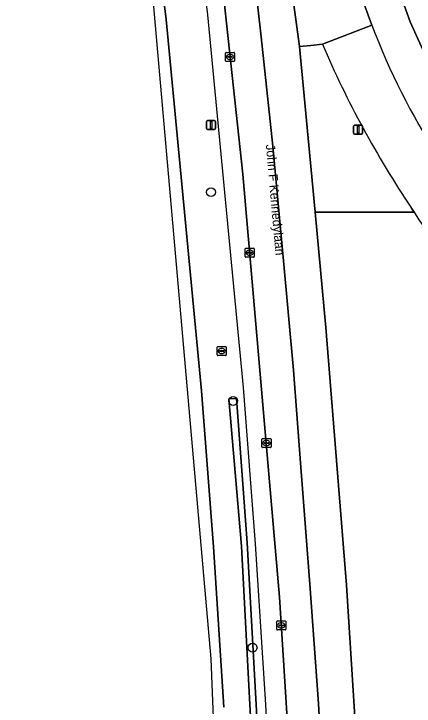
# Model space of a CAD drawing. Extents: x 162082 to 163401, y 388089 to 388636.
# Drawn here: x 162082.4 to 162126.4, y 388303.5 to 388379.6 of the extents above; entities that cross this region are included whole.
import ezdxf

# ---------------------------------------------------------------- set-up
doc = ezdxf.new("R2010")
doc.units = 0
for name, color, linetype in [('IMGEO_Berm_groen', 7, 'Continuous'), ('IMGEO_Boom', 7, 'Continuous'), ('IMGEO_Groenvoorziening', 7, 'Continuous'), ('IMGEO_Haag', 7, 'Continuous'), ('IMGEO_Hek', 7, 'Continuous'), ('IMGEO_Kolk', 7, 'Continuous'), ('IMGEO_Lichtmast', 7, 'Continuous'), ('IMGEO_Loofbos', 7, 'Continuous'), ('IMGEO_Openbare_ruimte_label', 7, 'Continuous'), ('IMGEO_Rijbaan_regionaal_gesloten', 7, 'Continuous'), ('IMGEO_Rioolput', 7, 'Continuous')]:
    doc.layers.add(name, color=color, linetype=linetype)

msp = doc.modelspace()

# ---------------------------------------------------------------- linework, layer by layer
at = {"layer": 'IMGEO_Berm_groen'}
for points in [[(162089.344, 388451.187), (162094.693, 388414.588), (162097.831, 388389.672), (162099.12, 388379.04), (162103.019, 388338.152), (162104.342, 388320.988), (162105.469, 388303.355)], [(162112.999, 388293.402), (162111.592, 388315.455), (162107.552, 388361.994), (162105.216, 388383.751), (162101.034, 388417.69), (162098.392, 388435.629)], [(162158.27, 388342.635), (162154.648, 388344.026), (162150.415, 388346.266), (162146.042, 388349.218), (162141.488, 388353.516), (162137.25, 388358.462), (162133.596, 388363.93), (162129.315, 388371.379), (162125.988, 388378.753), (162122.707, 388387.868), (162120.457, 388395.943), (162118.359, 388404.463), (162117.835, 388406.126), (162116.603, 388420.123), (162123.796, 388423.745), (162124.571, 388428.394), (162120.982, 388427.776)], [(162119.679, 388384.539), (162120.659, 388381.443), (162121.76, 388378.389)], [(162116.321, 388376.305), (162115.03, 388376.174), (162113.812, 388376.05), (162115.514, 388357.816), (162126.399, 388357.816), (162126.249, 388358.048), (162126.1, 388358.281)], [(162126.399, 388357.816), (162115.514, 388357.816), (162116.697, 388345.147), (162118.955, 388316.778), (162120.757, 388288.379), (162121.367, 388274.924), (162122.052, 388250), (162122.739, 388224.991), (162122.955, 388200.63), (162122.882, 388179.99), (162122.587, 388168.062), (162122.56, 388166.951), (162122.56, 388166.951)]]:
    msp.add_lwpolyline(points, dxfattribs=at)
msp.add_lwpolyline([(162110.975, 388250.254), (162110.214, 388270.794), (162108.335, 388303.624), (162107.41, 388321.076), (162106.04, 388337.271), (162106.888, 388337.32), (162108.037, 388321.434), (162109.051, 388303.654), (162110.766, 388270.838), (162111.602, 388250.03), (162111.788, 388226.246), (162111.192, 388226.261)], close=True, dxfattribs=at)
for centre, radius, start, end in [((162198.196, 388407.679), 81.856, 200.96672, 223.60171), ((162218.961, 388420.328), 111.683, 203.21481, 213.74967), ((162180.472, 388392.875), 64.444, 212.95842, 240.88748)]:
    msp.add_arc(centre, radius, start, end, dxfattribs=at)
at = {"layer": 'IMGEO_Boom'}
for centre in [(162104.072, 388360.026), (162106.505, 388337.049), (162108.638, 388309.893)]:
    msp.add_circle(centre, 0.489, dxfattribs=at)
at = {"layer": 'IMGEO_Groenvoorziening'}
msp.add_lwpolyline([(162108.037, 388321.434), (162106.888, 388337.32), (162106.04, 388337.271), (162107.41, 388321.076), (162108.335, 388303.624), (162110.214, 388270.794), (162110.975, 388250.254), (162111.192, 388226.261), (162111.788, 388226.246), (162111.602, 388250.03), (162110.766, 388270.838), (162109.051, 388303.654)], close=True, dxfattribs=at)
at = {"layer": 'IMGEO_Haag'}
msp.add_lwpolyline([(162108.037, 388321.434), (162106.888, 388337.32), (162106.04, 388337.271), (162107.41, 388321.076), (162108.335, 388303.624), (162110.214, 388270.794), (162110.975, 388250.254), (162111.192, 388226.261), (162111.788, 388226.246), (162111.602, 388250.03), (162110.766, 388270.838), (162109.051, 388303.654)], close=True, dxfattribs=at)
at = {"layer": 'IMGEO_Hek'}
msp.add_lwpolyline([(162102.26, 388391.365), (162103.693, 388379.543), (162107.603, 388338.54), (162108.931, 388321.311), (162110.061, 388303.626), (162111.787, 388270.809), (162112.468, 388250), (162113.297, 388223.395), (162112.358, 388168.71)], dxfattribs=at)
at = {"layer": 'IMGEO_Kolk'}
for p, q in [((162105.663, 388374.484), (162105.663, 388375.336)), ((162105.738, 388375.41), (162106.59, 388375.41)), ((162106.664, 388375.336), (162106.664, 388374.484)), ((162105.922, 388374.904), (162105.922, 388374.916)), ((162106.36, 388374.867), (162105.962, 388374.867)), ((162105.965, 388374.953), (162106.363, 388374.953)), ((162106.174, 388374.63), (162106.149, 388374.63)), ((162106.151, 388375.19), (162106.176, 388375.19)), ((162106.406, 388374.916), (162106.406, 388374.904)), ((162106.59, 388374.41), (162105.738, 388374.41)), ((162107.823, 388352.935), (162107.823, 388353.787)), ((162107.898, 388353.861), (162108.75, 388353.861)), ((162108.082, 388353.355), (162108.082, 388353.367)), ((162108.52, 388353.318), (162108.122, 388353.318)), ((162108.125, 388353.404), (162108.523, 388353.404)), ((162108.311, 388353.641), (162108.336, 388353.641)), ((162108.566, 388353.367), (162108.566, 388353.355)), ((162108.824, 388353.787), (162108.824, 388352.935)), ((162108.75, 388352.861), (162107.898, 388352.861)), ((162108.334, 388353.081), (162108.309, 388353.081)), ((162109.668, 388331.982), (162109.668, 388332.834)), ((162109.743, 388332.908), (162110.595, 388332.908)), ((162110.156, 388332.688), (162110.181, 388332.688)), ((162110.669, 388332.834), (162110.669, 388331.982)), ((162110.595, 388331.908), (162109.743, 388331.908)), ((162109.927, 388332.402), (162109.927, 388332.414)), ((162110.365, 388332.365), (162109.967, 388332.365)), ((162109.97, 388332.451), (162110.368, 388332.451)), ((162110.179, 388332.128), (162110.154, 388332.128)), ((162110.411, 388332.414), (162110.411, 388332.402)), ((162111.289, 388311.917), (162111.289, 388312.769)), ((162111.364, 388312.843), (162112.216, 388312.843)), ((162112.29, 388312.769), (162112.29, 388311.917)), ((162111.548, 388312.337), (162111.548, 388312.349)), ((162111.986, 388312.3), (162111.588, 388312.3)), ((162111.591, 388312.386), (162111.989, 388312.386)), ((162111.8, 388312.063), (162111.775, 388312.063)), ((162111.777, 388312.623), (162111.802, 388312.623)), ((162112.032, 388312.349), (162112.032, 388312.337)), ((162112.216, 388311.843), (162111.364, 388311.843))]:
    msp.add_line(p, q, dxfattribs=at)
for points in [[(162105.663, 388374.484), (162105.663, 388375.336)], [(162105.738, 388375.41), (162106.59, 388375.41)], [(162106.664, 388375.336), (162106.664, 388374.484)], [(162106.59, 388374.41), (162105.738, 388374.41)], [(162107.823, 388352.935), (162107.823, 388353.787)], [(162107.898, 388353.861), (162108.75, 388353.861)], [(162108.824, 388353.787), (162108.824, 388352.935)], [(162108.75, 388352.861), (162107.898, 388352.861)], [(162109.668, 388331.982), (162109.668, 388332.834)], [(162109.743, 388332.908), (162110.595, 388332.908)], [(162110.669, 388332.834), (162110.669, 388331.982)], [(162110.595, 388331.908), (162109.743, 388331.908)], [(162111.289, 388311.917), (162111.289, 388312.769)], [(162111.364, 388312.843), (162112.216, 388312.843)], [(162112.29, 388312.769), (162112.29, 388311.917)], [(162112.216, 388311.843), (162111.364, 388311.843)]]:
    msp.add_lwpolyline(points, dxfattribs=at)
for centre, radius, start, end in [((162105.74, 388375.334), 0.0765, 91.55205, 178.44795), ((162105.74, 388375.334), 0.0765, 91.55205, 178.44795), ((162106.588, 388375.334), 0.0765, 1.55205, 88.44795), ((162106.588, 388375.334), 0.0765, 1.55205, 88.44795), ((162105.74, 388374.486), 0.0765, 181.55205, 268.44795), ((162105.74, 388374.486), 0.0765, 181.55205, 268.44795), ((162105.962, 388374.913), 0.0403, 85.87752, 175.75265), ((162105.959, 388374.903), 0.0366, 178.93798, 274.71019), ((162106.363, 388374.91), 0.043, 264.86636, 352.45326), ((162106.367, 388374.915), 0.0386, 1.73085, 96.63898), ((162106.588, 388374.486), 0.0765, 271.55205, 358.44795), ((162106.588, 388374.486), 0.0765, 271.55205, 358.44795), ((162107.9, 388353.785), 0.0765, 91.55205, 178.44795), ((162107.9, 388353.785), 0.0765, 91.55205, 178.44795), ((162108.122, 388353.364), 0.0403, 85.87752, 175.75265), ((162108.119, 388353.354), 0.0366, 178.93798, 274.71019), ((162108.523, 388353.361), 0.043, 264.86636, 352.45326), ((162108.527, 388353.366), 0.0386, 1.73085, 96.63898), ((162108.748, 388353.785), 0.0765, 1.55205, 88.44795), ((162108.748, 388353.785), 0.0765, 1.55205, 88.44795), ((162107.9, 388352.937), 0.0765, 181.55205, 268.44795), ((162107.9, 388352.937), 0.0765, 181.55205, 268.44795), ((162108.748, 388352.937), 0.0765, 271.55205, 358.44795), ((162108.748, 388352.937), 0.0765, 271.55205, 358.44795), ((162109.745, 388332.832), 0.0765, 91.55205, 178.44795), ((162109.745, 388332.832), 0.0765, 91.55205, 178.44795), ((162110.593, 388332.832), 0.0765, 1.55205, 88.44795), ((162110.593, 388332.832), 0.0765, 1.55205, 88.44795), ((162109.745, 388331.984), 0.0765, 181.55205, 268.44795), ((162109.745, 388331.984), 0.0765, 181.55205, 268.44795), ((162109.967, 388332.411), 0.0403, 85.87752, 175.75265), ((162109.964, 388332.401), 0.0366, 178.93798, 274.71019), ((162110.368, 388332.408), 0.043, 264.86636, 352.45326), ((162110.372, 388332.413), 0.0386, 1.73085, 96.63898), ((162110.593, 388331.984), 0.0765, 271.55205, 358.44795), ((162110.593, 388331.984), 0.0765, 271.55205, 358.44795), ((162111.366, 388312.767), 0.0765, 91.55205, 178.44795), ((162111.366, 388312.767), 0.0765, 91.55205, 178.44795), ((162112.214, 388312.767), 0.0765, 1.55205, 88.44795), ((162112.214, 388312.767), 0.0765, 1.55205, 88.44795), ((162111.588, 388312.346), 0.0403, 85.87752, 175.75265), ((162111.585, 388312.336), 0.0366, 178.93798, 274.71019), ((162111.989, 388312.343), 0.043, 264.86636, 352.45326), ((162111.993, 388312.348), 0.0386, 1.73085, 96.63898), ((162111.366, 388311.919), 0.0765, 181.55205, 268.44795), ((162111.366, 388311.919), 0.0765, 181.55205, 268.44795), ((162112.214, 388311.919), 0.0765, 271.55205, 358.44795), ((162112.214, 388311.919), 0.0765, 271.55205, 358.44795)]:
    msp.add_arc(centre, radius, start, end, dxfattribs=at)
for centre, major_axis, ratio, start_param, end_param in [((162106.15, 388374.91), (-0.387, 0.002), 0.722429, 4.712389, 7.853982), ((162106.175, 388374.91), (-0.39, 0.002), 0.717154, 1.570796, 4.712389), ((162108.31, 388353.361), (-0.387, 0.002), 0.722429, 4.712389, 7.853982), ((162108.335, 388353.361), (-0.39, 0.002), 0.717154, 1.570796, 4.712389), ((162110.155, 388332.408), (-0.387, 0.002), 0.722429, 4.712389, 7.853982), ((162110.18, 388332.408), (-0.39, 0.002), 0.717154, 1.570796, 4.712389), ((162111.776, 388312.343), (-0.387, 0.002), 0.722429, 4.712389, 7.853982), ((162111.801, 388312.343), (-0.39, 0.002), 0.717154, 1.570796, 4.712389)]:
    msp.add_ellipse(centre, major_axis=major_axis, ratio=ratio, start_param=start_param, end_param=end_param, dxfattribs=at)
at = {"layer": 'IMGEO_Lichtmast'}
for p, q in [((162103.575, 388367.018), (162103.575, 388367.818)), ((162103.575, 388367.818), (162103.575, 388367.018)), ((162103.675, 388367.918), (162104.465, 388367.918)), ((162104.465, 388367.918), (162103.675, 388367.918)), ((162104.565, 388367.818), (162104.565, 388367.018)), ((162104.565, 388367.018), (162104.565, 388367.818)), ((162104.465, 388366.918), (162103.675, 388366.918)), ((162103.675, 388366.918), (162104.465, 388366.918)), ((162119.754, 388366.503), (162119.754, 388367.303)), ((162119.754, 388367.303), (162119.754, 388366.503)), ((162119.854, 388367.403), (162120.644, 388367.403)), ((162120.644, 388367.403), (162119.854, 388367.403)), ((162120.744, 388367.303), (162120.744, 388366.503)), ((162120.744, 388366.503), (162120.744, 388367.303)), ((162120.644, 388366.403), (162119.854, 388366.403)), ((162119.854, 388366.403), (162120.644, 388366.403))]:
    msp.add_line(p, q, dxfattribs=at)
for points in [[(162103.995, 388367.793), (162104.145, 388367.793), (162104.145, 388367.043), (162103.995, 388367.043), (162103.995, 388367.793)], [(162120.174, 388367.278), (162120.324, 388367.278), (162120.324, 388366.528), (162120.174, 388366.528), (162120.174, 388367.278)]]:
    msp.add_lwpolyline(points, dxfattribs=at)
for centre, start, end in [((162103.675, 388367.818), 90, 180), ((162103.675, 388367.818), 90, 180), ((162104.465, 388367.818), 0, 90), ((162104.465, 388367.818), 360, 90), ((162103.675, 388367.018), 180, 270), ((162103.675, 388367.018), 180, 270), ((162104.465, 388367.018), 270, 0), ((162104.465, 388367.018), 270, 0), ((162119.854, 388367.303), 90, 180), ((162119.854, 388367.303), 90, 180), ((162120.644, 388367.303), 0, 90), ((162120.644, 388367.303), 360, 90), ((162119.854, 388366.503), 180, 270), ((162119.854, 388366.503), 180, 270), ((162120.644, 388366.503), 270, 0), ((162120.644, 388366.503), 270, 0)]:
    msp.add_arc(centre, 0.1, start, end, dxfattribs=at)
at = {"layer": 'IMGEO_Loofbos'}
msp.add_lwpolyline([(162122.707, 388387.868), (162125.988, 388378.753), (162129.315, 388371.379), (162133.596, 388363.93), (162137.25, 388358.462), (162141.488, 388353.516), (162146.042, 388349.218), (162150.415, 388346.266), (162154.648, 388344.026), (162158.27, 388342.635), (162161.57, 388350.099), (162156.979, 388353.85), (162147.415, 388362.089), (162142.644, 388366.768), (162138.571, 388371.829), (162136.086, 388376.918), (162133.229, 388383.937)], dxfattribs=at)
at = {"layer": 'IMGEO_Rijbaan_regionaal_gesloten'}
for points in [[(162097.342, 388483.552), (162097.937, 388480.815), (162099.911, 388470.651), (162101.923, 388458.981), (162102.512, 388455.565), (162104.378, 388443.581), (162110.89, 388397.377), (162113.812, 388376.05), (162115.03, 388376.174), (162116.321, 388376.305), (162121.76, 388378.389), (162120.659, 388381.443), (162119.679, 388384.539)], [(162082.384, 388478.59), (162096.95, 388389.672), (162104.064, 388308.678), (162106.934, 388235.552)], [(162105.469, 388303.355), (162104.342, 388320.988), (162103.019, 388338.152), (162099.12, 388379.04), (162097.831, 388389.672), (162094.693, 388414.588), (162089.344, 388451.187)], [(162120.757, 388288.379), (162118.955, 388316.778), (162116.697, 388345.147), (162115.514, 388357.816), (162113.812, 388376.05), (162110.89, 388397.377), (162104.378, 388443.581)], [(162098.392, 388435.629), (162101.034, 388417.69), (162105.216, 388383.751), (162107.552, 388361.994), (162111.592, 388315.455), (162112.999, 388293.402)], [(162102.152, 388434.347), (162103.955, 388421.825), (162105.233, 388412.199), (162107.036, 388398.174), (162108.539, 388386.292), (162109.591, 388377.103), (162110.869, 388365.071), (162111.996, 388352.888), (162113.124, 388340.453), (162113.951, 388329.774), (162114.929, 388316.873), (162115.906, 388303.755), (162117.183, 388280.066)], [(162117.183, 388280.066), (162115.906, 388303.755), (162114.929, 388316.873), (162113.951, 388329.774), (162113.124, 388340.453), (162111.996, 388352.888), (162110.869, 388365.071), (162109.591, 388377.103), (162108.539, 388386.292), (162107.036, 388398.174), (162105.233, 388412.199), (162103.955, 388421.825), (162102.152, 388434.347)], [(162121.76, 388378.389), (162116.321, 388376.305)], [(162126.1, 388358.281), (162126.249, 388358.048), (162126.399, 388357.816)]]:
    msp.add_lwpolyline(points, dxfattribs=at)
for centre, radius, start, end in [((162198.196, 388407.679), 81.856, 200.96672, 223.60171), ((162218.961, 388420.328), 111.683, 203.21481, 213.74967), ((162180.472, 388392.875), 64.444, 212.95842, 240.88748)]:
    msp.add_arc(centre, radius, start, end, dxfattribs=at)
at = {"layer": 'IMGEO_Rioolput'}
for p, q in [((162104.743, 388342.114), (162104.743, 388342.966)), ((162104.818, 388343.04), (162105.67, 388343.04)), ((162105.002, 388342.534), (162105.002, 388342.546)), ((162105.44, 388342.497), (162105.042, 388342.497)), ((162105.045, 388342.583), (162105.443, 388342.583)), ((162105.231, 388342.82), (162105.256, 388342.82)), ((162105.486, 388342.546), (162105.486, 388342.534)), ((162105.744, 388342.966), (162105.744, 388342.114)), ((162105.67, 388342.04), (162104.818, 388342.04)), ((162105.254, 388342.26), (162105.229, 388342.26))]:
    msp.add_line(p, q, dxfattribs=at)
for points in [[(162104.743, 388342.114), (162104.743, 388342.966)], [(162104.818, 388343.04), (162105.67, 388343.04)], [(162105.744, 388342.966), (162105.744, 388342.114)], [(162105.67, 388342.04), (162104.818, 388342.04)]]:
    msp.add_lwpolyline(points, dxfattribs=at)
for centre, radius, start, end in [((162104.82, 388342.964), 0.0765, 91.55205, 178.44795), ((162104.82, 388342.964), 0.0765, 91.55205, 178.44795), ((162105.042, 388342.543), 0.0403, 85.87752, 175.75265), ((162105.039, 388342.533), 0.0366, 178.93798, 274.71019), ((162105.443, 388342.54), 0.043, 264.86636, 352.45326), ((162105.447, 388342.545), 0.0386, 1.73085, 96.63898), ((162105.668, 388342.964), 0.0765, 1.55205, 88.44795), ((162105.668, 388342.964), 0.0765, 1.55205, 88.44795), ((162104.82, 388342.116), 0.0765, 181.55205, 268.44795), ((162104.82, 388342.116), 0.0765, 181.55205, 268.44795), ((162105.668, 388342.116), 0.0765, 271.55205, 358.44795), ((162105.668, 388342.116), 0.0765, 271.55205, 358.44795)]:
    msp.add_arc(centre, radius, start, end, dxfattribs=at)
for centre, major_axis, ratio, start_param, end_param in [((162105.23, 388342.54), (-0.387, 0.002), 0.722429, 4.712389, 7.853982), ((162105.255, 388342.54), (-0.39, 0.002), 0.717154, 1.570796, 4.712389)]:
    msp.add_ellipse(centre, major_axis=major_axis, ratio=ratio, start_param=start_param, end_param=end_param, dxfattribs=at)

# ---------------------------------------------------------------- texts
at = {"layer": 'IMGEO_Openbare_ruimte_label'}
msp.add_text('John F Kennedylaan', height=1, rotation=275.04917, dxfattribs=at).set_placement((162110.093, 388365.251))

doc.saveas('drawing.dxf')
